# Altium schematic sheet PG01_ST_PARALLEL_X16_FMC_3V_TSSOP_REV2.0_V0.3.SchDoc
size C
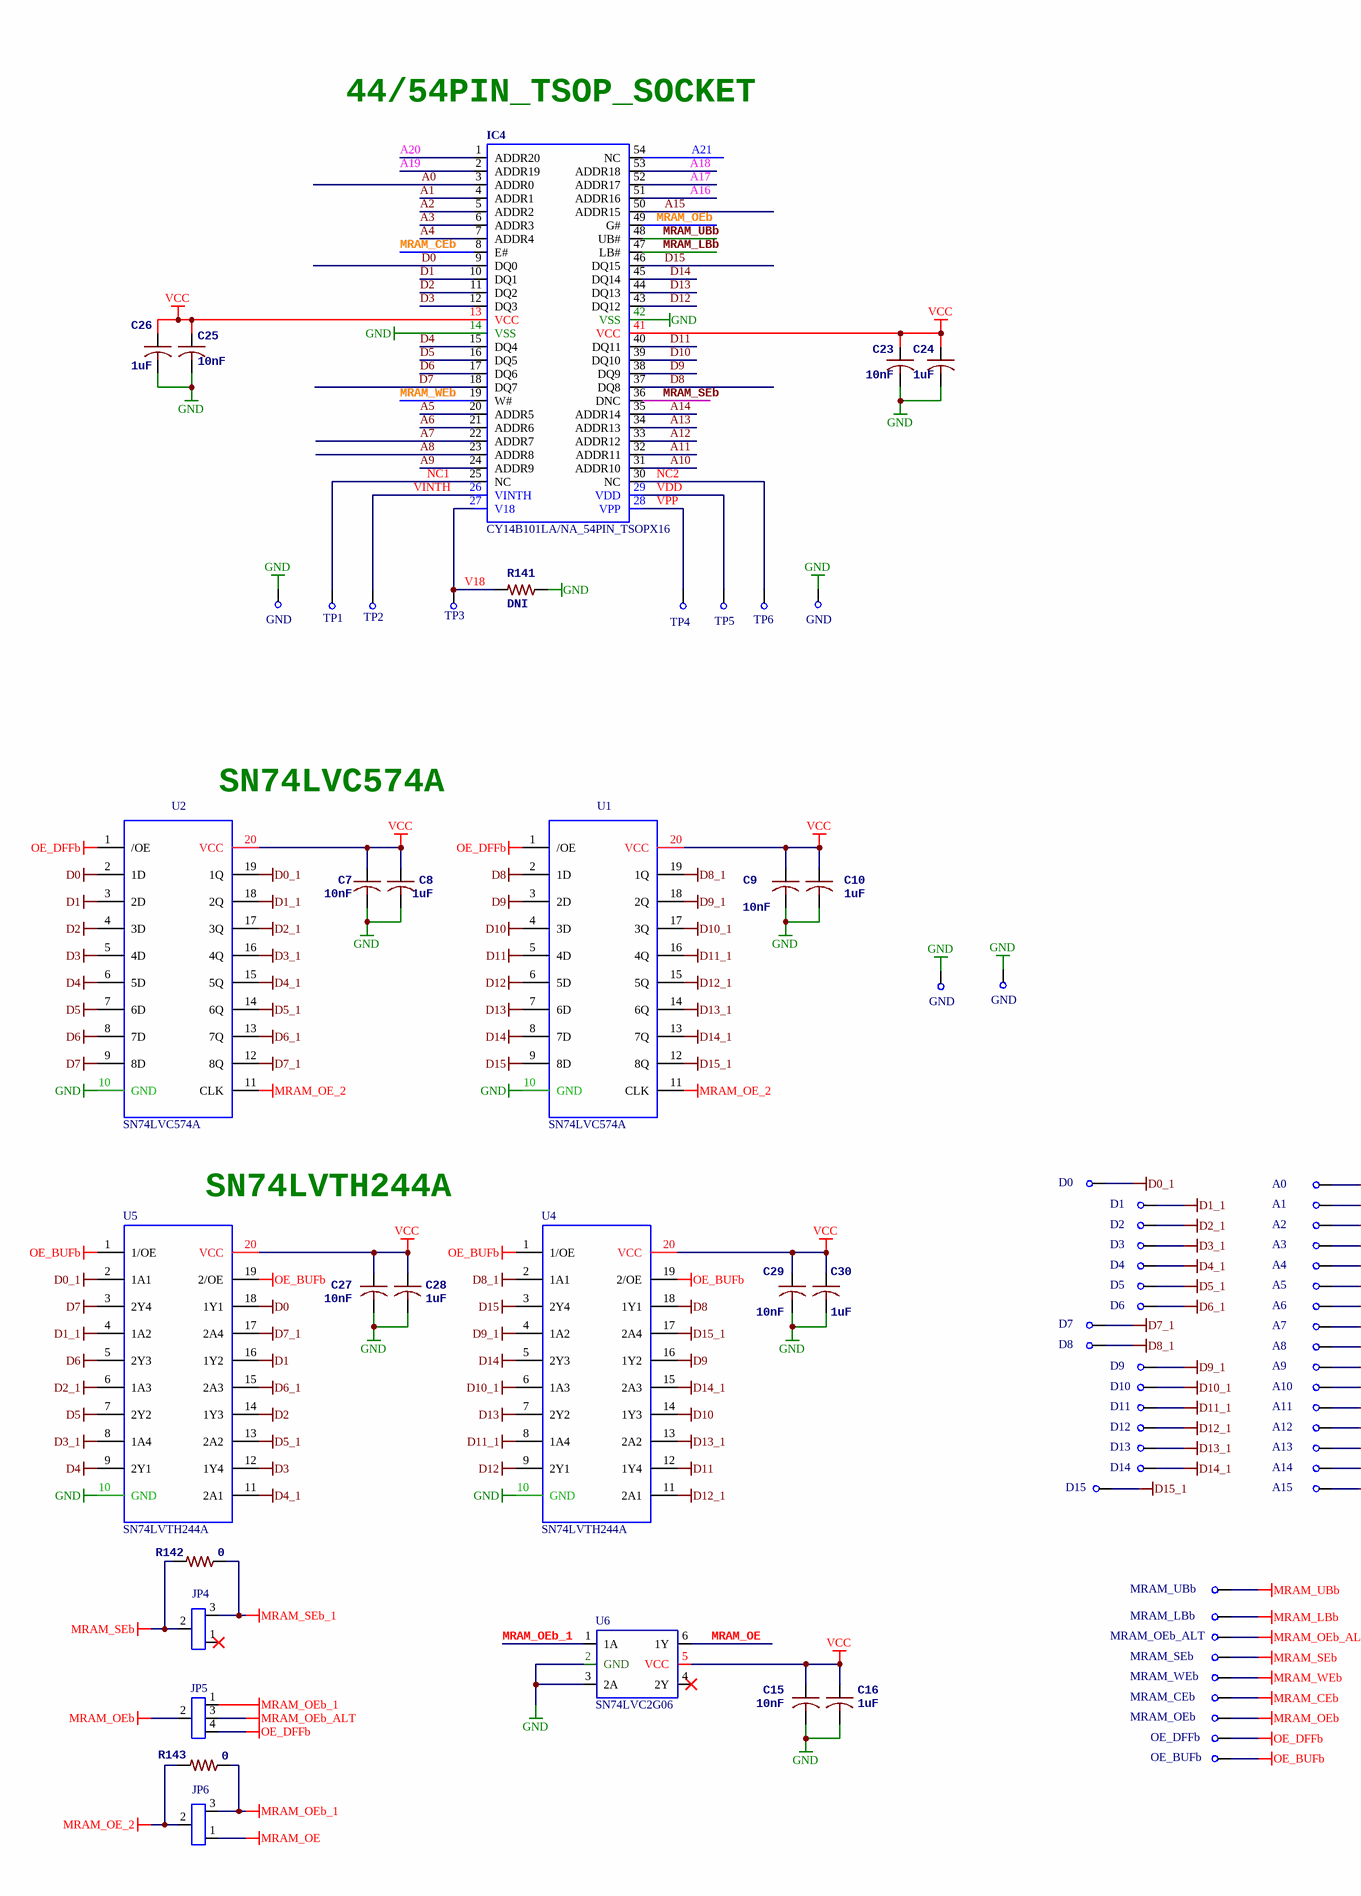
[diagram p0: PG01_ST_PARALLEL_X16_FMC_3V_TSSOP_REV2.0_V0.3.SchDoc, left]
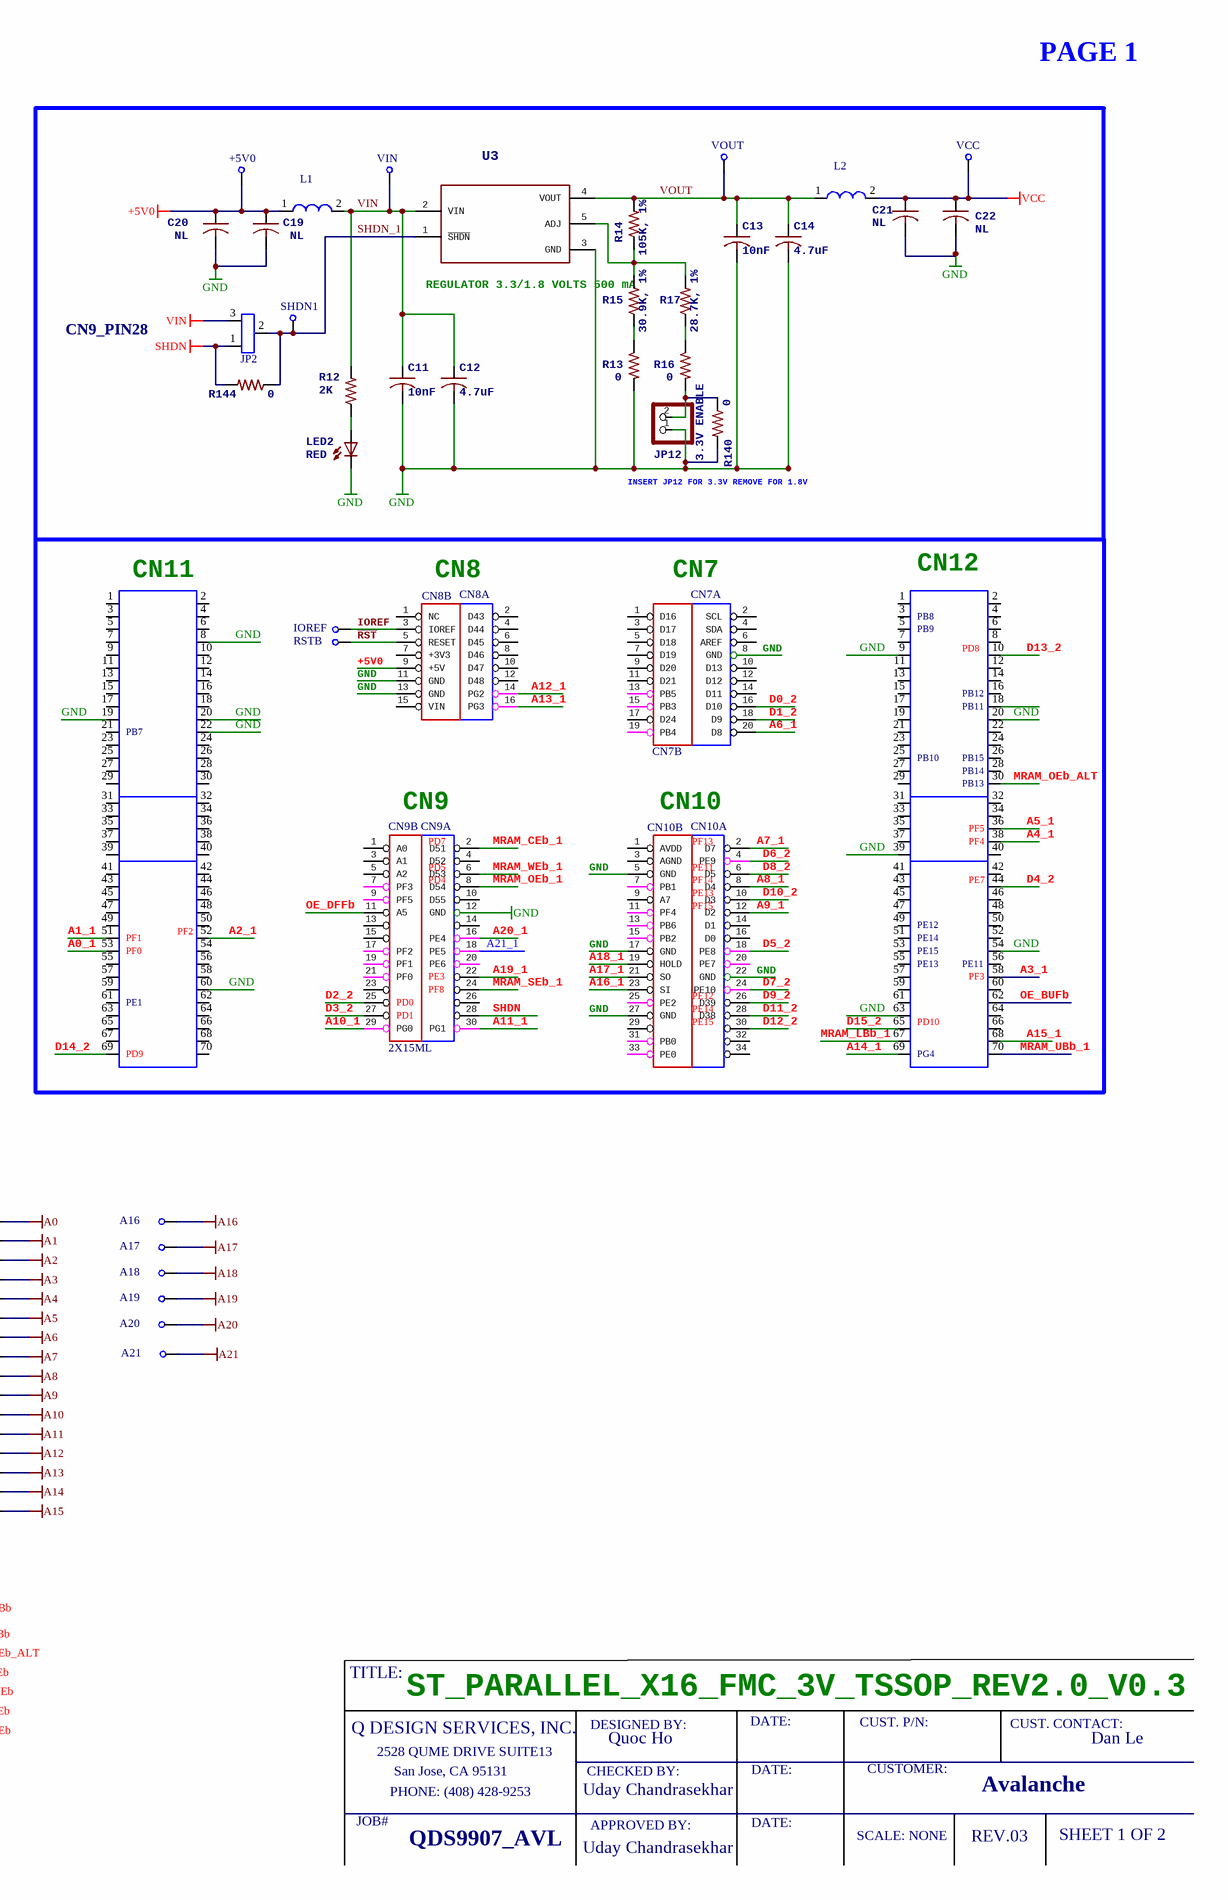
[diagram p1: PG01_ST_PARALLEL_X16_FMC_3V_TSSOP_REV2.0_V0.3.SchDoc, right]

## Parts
+5V0  TP  [TEST POINT]  (value not drawn)
A0  TP  [TEST POINT]  (value not drawn)
A1  TP  [TEST POINT]  (value not drawn)
A2  TP  [TEST POINT]  (value not drawn)
A3  TP  [TEST POINT]  (value not drawn)
A4  TP  [TEST POINT]  (value not drawn)
A5  TP  [TEST POINT]  (value not drawn)
A6  TP  [TEST POINT]  (value not drawn)
A7  TP  [TEST POINT]  (value not drawn)
A8  TP  [TEST POINT]  (value not drawn)
A9  TP  [TEST POINT]  (value not drawn)
A10  TP  [TEST POINT]  (value not drawn)
A11  TP  [TEST POINT]  (value not drawn)
A12  TP  [TEST POINT]  (value not drawn)
A13  TP  [TEST POINT]  (value not drawn)
A14  TP  [TEST POINT]  (value not drawn)
A15  TP  [TEST POINT]  (value not drawn)
A16  TP  [TEST POINT]  (value not drawn)
A17  TP  [TEST POINT]  (value not drawn)
A18  TP  [TEST POINT]  (value not drawn)
A19  TP  [TEST POINT]  (value not drawn)
A20  TP  [TEST POINT]  (value not drawn)
A21  TP  [TEST POINT]  (value not drawn)
C7  10nF  [N_0603]
C8  1uF  [N_0603]
C9  10nF  [N_0603]
C10  1uF  [N_0603]
C11  10nF  [N_0603]
C12  4.7uF  [N_0603]
C13  10nF  [N_0603]
C14  4.7uF  [N_0603]
C15  10nF  [N_0603]
C16  1uF  [N_0603]
C19  NL  [0603]
C20  NL  [0603]
C21  NL  [0603]
C22  NL  [0603]
C23  10nF  [N_0603]
C24  1uF  [N_0603]
C25  10nF  [N_0603]
C26  1uF  [N_0603]
C27  10nF  [N_0603]
C28  1uF  [N_0603]
C29  10nF  [N_0603]
C30  1uF  [N_0603]
CN7  2X10_ML  [2X10-HEADER]  (value not drawn)  (parts A,B of 2)
CN8  2X8_ML  [2X8-HEADER]  (value not drawn)  (parts A,B of 2)
CN9  2X15ML  [2X15-HEADER]  (value not drawn)  (parts A,B of 2)
CN10  2X17ML  [2X17-HEADER]  (value not drawn)  (parts A,B of 2)
CN11  HDR2X35  [2X15X2-HEADER_CUSTOM]  (value not drawn)
CN12  HDR2X35  [2X15X2-HEADER_CUSTOM]  (value not drawn)
D0  TP  [TEST POINT]  (value not drawn)
D1  TP  [TEST POINT]  (value not drawn)
D2  TP  [TEST POINT]  (value not drawn)
D3  TP  [TEST POINT]  (value not drawn)
D4  TP  [TEST POINT]  (value not drawn)
D5  TP  [TEST POINT]  (value not drawn)
D6  TP  [TEST POINT]  (value not drawn)
D7  TP  [TEST POINT]  (value not drawn)
D8  TP  [TEST POINT]  (value not drawn)
D9  TP  [TEST POINT]  (value not drawn)
D10  TP  [TEST POINT]  (value not drawn)
D11  TP  [TEST POINT]  (value not drawn)
D12  TP  [TEST POINT]  (value not drawn)
D13  TP  [TEST POINT]  (value not drawn)
D14  TP  [TEST POINT]  (value not drawn)
D15  TP  [TEST POINT]  (value not drawn)
GND2  GND  [TEST POINT]
GND3  GND  [TEST POINT]
GND4  GND  [TEST POINT]
GND5  GND  [TEST POINT]
IC4  CY14B101LA/NA_54PIN_TSOPX16  [54PIN_TSOP_SOCKET_CUSTOM]
IOREF  TP  [TEST POINT]  (value not drawn)
JP2  3PIN_JUMPER  [1X3 MALE HEADER WITH SHUNT_071513]  (value not drawn)
JP4  3PIN_JUMPER  [1X3 MALE HEADER WITH SHUNT_071513]  (value not drawn)
JP5  4PIN_JUMPER  [1X4_HDR]  (value not drawn)
JP6  3PIN_JUMPER  [1X3 MALE HEADER WITH SHUNT_071513]  (value not drawn)
JP12  3.3V ENABLE  [1X2 HEADER WITH SHUNT_051914]
L1  (no value)  [0603]
L2  (no value)  [0603]
LED2  RED  [LED 0805 GREEN_032906]
MRAM_CEb  TESTPOINT  [TEST POINT]  (value not drawn)
MRAM_LBb  TESTPOINT  [TEST POINT]  (value not drawn)
MRAM_OEb  TP  [TEST POINT]  (value not drawn)
MRAM_OEb_ALT  TESTPOINT  [TEST POINT]  (value not drawn)
MRAM_SEb  TESTPOINT  [TEST POINT]  (value not drawn)
MRAM_UBb  TESTPOINT  [TEST POINT]  (value not drawn)
MRAM_WEb  TESTPOINT  [TEST POINT]  (value not drawn)
OE_BUFb  TP  [TEST POINT]  (value not drawn)
OE_DFFb  TP  [TEST POINT]  (value not drawn)
R12  2K  [N_0603]
R13  0  [N_0603]
R14  105K, 1%  [N_0603]
R15  30.9K, 1%  [N_0603]
R16  0  [N_0603]
R17  28.7K, 1%  [N_0603]
R140  0  [N_0603]
R141  DNI  [N_0603]
R142  0  [N_0603]
R143  0  [N_0603]
R144  0  [N_0603]
RSTB  TP  [TEST POINT]  (value not drawn)
SHDN1  TP  [TEST POINT]  (value not drawn)
TP1  TP  [TEST POINT]  (value not drawn)
TP2  TP  [TEST POINT]  (value not drawn)
TP3  TP  [TEST POINT]  (value not drawn)
TP4  TP  [TEST POINT]  (value not drawn)
TP5  TP  [TEST POINT]  (value not drawn)
TP6  TP  [TEST POINT]  (value not drawn)
U1  SN74LVC574A  [R-PDSO-G20]
U2  SN74LVC574A  [R-PDSO-G20]
U3  (no value)  [SOT223-6 REGULATOR_010419]
U4  SN74LVTH244A  [DB0020A]
U5  SN74LVTH244A  [DB0020A]
U6  SN74LVC2G06  [SOT-23]
VCC  TP  [TEST POINT]  (value not drawn)
VIN  TP  [TEST POINT]  (value not drawn)
VOUT  TP  [TEST POINT]  (value not drawn)

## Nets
+5V0: +5V0.1(TP1) C19.1 C20.1 CN8.9(+5V) L1.1
A0: A0.1(TP1) IC4.3(ADDR0)
A1: A1.1(TP1) IC4.4(ADDR1)
A2: A2.1(TP1) IC4.5(ADDR2)
A3: A3.1(TP1) IC4.6(ADDR3)
A4: A4.1(TP1) IC4.7(ADDR4)
A5: A5.1(TP1) IC4.20(ADDR5)
A6: A6.1(TP1) IC4.21(ADDR6)
A7: A7.1(TP1) IC4.22(ADDR7)
A8: A8.1(TP1) IC4.23(ADDR8)
A9: A9.1(TP1) IC4.24(ADDR9)
A10: A10.1(TP1) IC4.31(ADDR10)
A11: A11.1(TP1) IC4.32(ADDR11)
A12: A12.1(TP1) IC4.33(ADDR12)
A13: A13.1(TP1) IC4.34(ADDR13)
A14: A14.1(TP1) IC4.35(ADDR14)
A15: A15.1(TP1) IC4.50(ADDR15)
A16: A16.1(TP1) IC4.51(ADDR16)
A17: A17.1(TP1) IC4.52(ADDR17)
A18: A18.1(TP1) IC4.53(ADDR18)
A19: A19.1(TP1) IC4.2(ADDR19)
A20: A20.1(TP1) IC4.1(ADDR20)
A21: A21.1(TP1) IC4.54(NC)
D0: IC4.9(DQ0) U2.2(1D) U5.18(1Y1)
D0_1: D0.1(TP1) U2.19(1Q) U5.2(1A1)
D1: IC4.10(DQ1) U2.3(2D) U5.16(1Y2)
D1_1: D1.1(TP1) U2.18(2Q) U5.4(1A2)
D2: IC4.11(DQ2) U2.4(3D) U5.14(1Y3)
D2_1: D2.1(TP1) U2.17(3Q) U5.6(1A3)
D3: IC4.12(DQ3) U2.5(4D) U5.12(1Y4)
D3_1: D3.1(TP1) U2.16(4Q) U5.8(1A4)
D4: IC4.15(DQ4) U2.6(5D) U5.9(2Y1)
D4_1: D4.1(TP1) U2.15(5Q) U5.11(2A1)
D5: IC4.16(DQ5) U2.7(6D) U5.7(2Y2)
D5_1: D5.1(TP1) U2.14(6Q) U5.13(2A2)
D6: IC4.17(DQ6) U2.8(7D) U5.5(2Y3)
D6_1: D6.1(TP1) U2.13(7Q) U5.15(2A3)
D7: IC4.18(DQ7) U2.9(8D) U5.3(2Y4)
D7_1: D7.1(TP1) U2.12(8Q) U5.17(2A4)
D8: IC4.37(DQ8) U1.2(1D) U4.18(1Y1)
D8_1: D8.1(TP1) U1.19(1Q) U4.2(1A1)
D9: IC4.38(DQ9) U1.3(2D) U4.16(1Y2)
D9_1: D9.1(TP1) U1.18(2Q) U4.4(1A2)
D10: IC4.39(DQ10) U1.4(3D) U4.14(1Y3)
D10_1: D10.1(TP1) U1.17(3Q) U4.6(1A3)
D11: IC4.40(DQ11) U1.5(4D) U4.12(1Y4)
D11_1: D11.1(TP1) U1.16(4Q) U4.8(1A4)
D12: IC4.43(DQ12) U1.6(5D) U4.9(2Y1)
D12_1: D12.1(TP1) U1.15(5Q) U4.11(2A1)
D13: IC4.44(DQ13) U1.7(6D) U4.7(2Y2)
D13_1: D13.1(TP1) U1.14(6Q) U4.13(2A2)
D14: IC4.45(DQ14) U1.8(7D) U4.5(2Y3)
D14_1: D14.1(TP1) U1.13(7Q) U4.15(2A3)
D15: IC4.46(DQ15) U1.9(8D) U4.3(2Y4)
D15_1: D15.1(TP1) U1.12(8Q) U4.17(2A4)
GND: C7.2 C8.2 C9.2 C10.2 C11.2 C12.2 C13.2 C14.2 C15.2 C16.2 C19.2 C20.2 C21.2 C22.2 C23.2 C24.2 C25.2 C26.2 C27.2 C28.2 C29.2 C30.2 CN7.8(GND) CN8.11(GND) CN8.13(GND) CN9.12(GND) CN10.5(GND) CN10.17(GND) CN10.22(GND) CN10.27(GND) CN11.8 CN11.19 CN11.20 CN11.22 CN11.60 CN12.9 CN12.20 CN12.39 CN12.54 CN12.63 GND2.1(TP1) GND3.1(TP1) GND4.1(TP1) GND5.1(TP1) IC4.14(VSS) IC4.42(VSS) JP12.1 LED2.C R13.2 R140.2 R141.1 U1.10(GND) U2.10(GND) U3.3(GND) U4.10(GND) U5.10(GND) U6.2(GND) U6.3(2A)
MRAM_CEb: IC4.8(E#) MRAM_CEb.1(TP1)
MRAM_LBb: IC4.47(LB#) MRAM_LBb.1(TP1)
MRAM_OE: JP6.1 U6.6(1Y)
MRAM_OE_2: JP6.2 R143.2 U1.11(CLK) U2.11(CLK)
MRAM_OEb: IC4.49(G#) JP5.2 MRAM_OEb.1(TP1)
MRAM_OEb_1: CN9.8(D54) JP5.1 JP6.3 R143.1 U6.1(1A)
MRAM_OEb_ALT: CN12.30 JP5.3 MRAM_OEb_ALT.1(TP1)
MRAM_SEb: IC4.36(DNC) JP4.2 MRAM_SEb.1(TP1) R142.2
MRAM_SEb_1: CN9.24 JP4.3 R142.1
MRAM_UBb: IC4.48(UB#) MRAM_UBb.1(TP1)
MRAM_WEb: IC4.19(W#) MRAM_WEb.1(TP1)
OE_BUFb: CN12.62 OE_BUFb.1(TP1) U4.1(1/OE) U4.19(2/OE) U5.1(1/OE) U5.19(2/OE)
OE_DFFb: CN9.11(A5) JP5.4 OE_DFFb.1(TP1) U1.1(/OE) U2.1(/OE)
SHDN: CN9.28 JP2.1 R144.2
VCC: C7.1 C8.1 C9.1 C10.1 C15.1 C16.1 C21.1 C22.1 C23.1 C24.1 C25.1 C26.1 C27.1 C28.1 C29.1 C30.1 IC4.13(VCC) IC4.41(VCC) L2.2 U1.20(VCC) U2.20(VCC) U4.20(VCC) U5.20(VCC) U6.5(VCC) VCC.1(TP1)
VIN: C11.1 C12.1 JP2.3 L1.2 R12.2 U3.2(VIN) VIN.1(TP1)
A0_1: CN11.53
A1_1: CN11.51
A2_1: CN11.52
A3_1: CN12.58
A4_1: CN12.38
A5_1: CN12.36
A6_1: CN7.20(D8)
A7_1: CN10.2(D7)
A8_1: CN10.8(D4)
A9_1: CN10.12(D2)
A10_1: CN9.29(PG0)
A11_1: CN9.30(PG1)
A12_1: CN8.14(PG2)
A13_1: CN8.16(PG3)
A14_1: CN12.69
A15_1: CN12.68
A16_1: CN10.23(SI)
A17_1: CN10.21(SO)
A18_1: CN10.19(HOLD)
A19_1: CN9.22
A20_1: CN9.16(PE4)
A21_1: CN9.18(PE5)
D0_2: CN7.16(D10)
D1_2: CN7.18(D9)
D2_2: CN9.25
D3_2: CN9.27
D4_2: CN12.44
D5_2: CN10.18(PE8)
D6_2: CN10.4(PE9)
D7_2: CN10.24(PE10)
D8_2: CN10.6(D5)
D9_2: CN10.26(D39)
D10_2: CN10.10(D3)
D11_2: CN10.28(D38)
D12_2: CN10.30
D13_2: CN12.10
D14_2: CN11.69
D15_2: CN12.65
IOREF: CN8.3(IOREF) IOREF.1(TP1)
MRAM_CEb_1: CN9.2(D51)
MRAM_LBb_1: CN12.67
MRAM_UBb_1: CN12.70
MRAM_WEb_1: CN9.6(D53)
NC1: IC4.25(NC) TP1.1(TP1)
NC2: IC4.30(NC) TP6.1(TP1)
~{RST}: CN8.5(RESET) RSTB.1(TP1)
SHDN_1: JP2.2 R144.1 SHDN1.1(TP1) U3.1(~{SHDN})
V18: IC4.27(V18) R141.2 TP3.1(TP1)
VDD: IC4.29(VDD) TP5.1(TP1)
VINTH: IC4.26(VINTH) TP2.1(TP1)
VOUT: C13.1 C14.1 L2.1 R14.2 U3.4(VOUT) VOUT.1(TP1)
VPP: IC4.28(VPP) TP4.1(TP1)
NetJP12_2: JP12.2 R16.2 R140.1
NetLED2_A: LED2.A R12.1
NetR13_1: R13.1 R15.1
NetR14_1: R14.1 R15.2 R17.2 U3.5(ADJ)
NetR16_1: R16.1 R17.1

Not connected (* = marked no-connect by the designer): CN7 1(D16) 2(SCL) 3(D17) 4(SDA) 5(D18) 6(AREF) 7(D19) 9(D20) 10(D13) 11(D21) 12(D12) 13(PB5) 14(D11) 15(PB3) 17(D24) 19(PB4); CN8 1(NC) 2(D43) 4(D44) 6(D45) 7(+3V3) 8(D46) 10(D47) 12(D48) 15(VIN); CN9 1(A0) 3(A1) 4(D52) 5(A2) 7(PF3) 9(PF5) 10(D55) 13 14 15 17(PF2) 19(PF1) 20(PE6) 21(PF0) 23 26; CN10 1(AVDD) 3(AGND) 7(PB1) 9(A7) 11(PF4) 13(PB6) 14(D1) 15(PB2) 16(D0) 20(PE7) 25(PE2) 29 31(PB0) 32 33(PE0) 34; CN11 1 2 3 4 5 6 7 9 10 11 12 13 14 15 16 17 18 21 23 24 25 26 27 28 29 30 31 32 33 34 35 36 37 38 39 40 41 42 43 44 45 46 47 48 49 50 54 55 56 57 58 59 61 62 63 64 65 66 67 68 70; CN12 1 2 3 4 5 6 7 8 11 12 13 14 15 16 17 18 19 21 22 23 24 25 26 27 28 29 31 32 33 34 35 37 40 41 42 43 45 46 47 48 49 50 51 52 53 55 56 57 59 60 61 64 66; JP4 1*; U6 4(2Y)*

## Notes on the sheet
- PAGE 1
- (near IC4) 44/54PIN_TSOP_SOCKET
- REGULATOR 3.3/1.8 VOLTS
  500 mA
- CN9_PIN28
- INSERT JP12 FOR 3.3V
  REMOVE FOR 1.8V
- (near CN8) CN8
- (near CN7) CN7
- (near CN12) PB8
- (near CN12) PB9
- (near CN12) PB12
- (near CN12) PD8
- (near CN11) PB7
- (near CN12) PB10
- (near CN12) PB11
- (near CN12) PB15
- (near CN12) PB14
- (near CN9) CN9
- (near CN10) CN10
- (near CN12) PB13
- (near CN12) PF5
- (near U2) SN74LVC574A
- (near CN9) PD4
- (near CN9) PD5
- (near CN9) PD7
- (near CN10) PF13
- (near CN10) PF14
- (near CN10) PE11
- (near CN10) PE13
- (near CN12) PF4
- (near CN12) PE7
- (near CN11) PF0
- (near CN11) PF1
- (near CN11) PF2
- (near CN10) PF15
- (near CN12) PE12
- (near CN12) PE14
- (near CN12) PE15
- (near CN11) PE1
- (near CN9) PD0
- (near CN9) PD1
- (near CN9) PE3
- (near CN9) PF8
- (near CN10) PE12
- (near CN10) PE15
- (near CN10) PE14
- (near CN12) PE13
- (near CN12) PD10
- (near CN12) PE11
- (near CN12) PF3
- (near CN11) PD9
- (near CN12) PG4
- (near U5) SN74LVTH244A
- TITLE:
- Q DESIGN SERVICES, INC.
- ST_PARALLEL_X16_FMC_3V_TSSOP_REV2.0_V0.3
- DESIGNED BY:
- DATE:
- CUST. P/N:
- CUST. CONTACT:
- 2528 QUME DRIVE SUITE13
- PHONE: (408) 428-9253
- San Jose, CA 95131
- Uday Chandrasekhar
- CHECKED BY:
- Quoc Ho
- CUSTOMER:
- Avalanche
- Dan Le
- JOB#
- QDS9907_AVL
- APPROVED BY:
- SCALE: NONE
- REV.03
- SHEET 1 OF 2

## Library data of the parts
+5V0 A0-A21 D0-D15 GND2-GND5 IOREF MRAM_CEb MRAM_LBb MRAM_OEb MRAM_OEb_ALT MRAM_SEb MRAM_UBb MRAM_WEb OE_BUFb OE_DFFb RSTB SHDN1 TP1-TP6 VCC VIN VOUT = TEST POINT 1: VALUE: COPPER FEATURE
C7 C9 C13 C23 C25 C27 C29 = C-USC0603: CAP CER 10000PF 25V X7R 0603; VALUE: CL10B103KA8NNNC; MAN: Samsung Electro-Mechanics
C8 C10 C24 C26 C28 C30 = C-USC0603: CAP CER 1UF 25V X7R 0603; VALUE: CL10B105KA8NFNC; MAN: Samsung Electro-Mechanics
C11 C15 = C-USC0603: CAP CER 10000PF 25V X7R 0603
C12 = C-USC0603: CAP CER 4.7UF 6.3V X7R 0603
C14 = C-USC0603: CAP CER 4.7UF 6.3V X7R 0603; MAN: Samsung Electro-Mechanics; VALUE: CL10B475KQ8NQNC
C16 = C-USC0603: CAP CER 1UF 25V X7R 0603
C19-C22 = C-USC0805
JP2 JP4 JP6 = 3PIN_JUMPER: DNI
JP5 = 4PIN_JUMPER: DNI
JP12 = PINHD-1X2: DNI; Part No.: 22284360; DESC: CONN HEADER VERT 36POS 2.54MM; MAN: Molex, LLC; VALUE: 0022284360
L1 L2 = FB: FERRITE BEAD 120 OHM 0603 1LN
LED2 = LEDCHIP-LED0805: LED RED CLEAR 0805 SMD; Part No.: 150080RS75000; MAN: Wurth Electronics Inc.; VALUE: 150080GS75000
R12 = R-US_R0603: RES SMD 2K OHM 1% 1/10W 0603
R13 R16 = R-US_R0603: RES SMD 0 OHM JUMPER 1/10W 0603; MAN: Panasonic Electronic Components; VALUE: ERJ-3GEY0R00V
R14 = R-US_R0603: RES SMD 105K OHM 1% 1/10W 0603
R15 = R-US_R0603: RES SMD 30.9K OHM 1% 1/10W 0603; VALUE: ERJ-3EKF3092V; MAN: Panasonic Electronic Components
R17 = R-US_R0603: RES SMD 28.7K OHM 1% 1/10W 0603; VALUE: ERJ-3EKF2872V; MAN: Panasonic Electronic Components
R140 R142-R144 = R-US_R0603: RES SMD 0 OHM JUMPER 1/10W 0603; Part No.: ERJ-3GEY0R00V
R141 = R-US_R0603
U1 U2 = SN74LVC574A: IC FF D-TYPE SNGL 8BIT 20TSSOP; Part No.: SN74LVC574APW
U3 = MCP1825T-ADJE/DC: IC REG LIN POS ADJ 500MA SOT223
U4 U5 = SN74LVTH244A: IC BUF NON-INVERT 3.6V 20SSOP; Part No.: SN74LVTH244ADB
U6 = SN74LVC2G06: Buffers & Line Drivers Dual w/ Open-Drain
